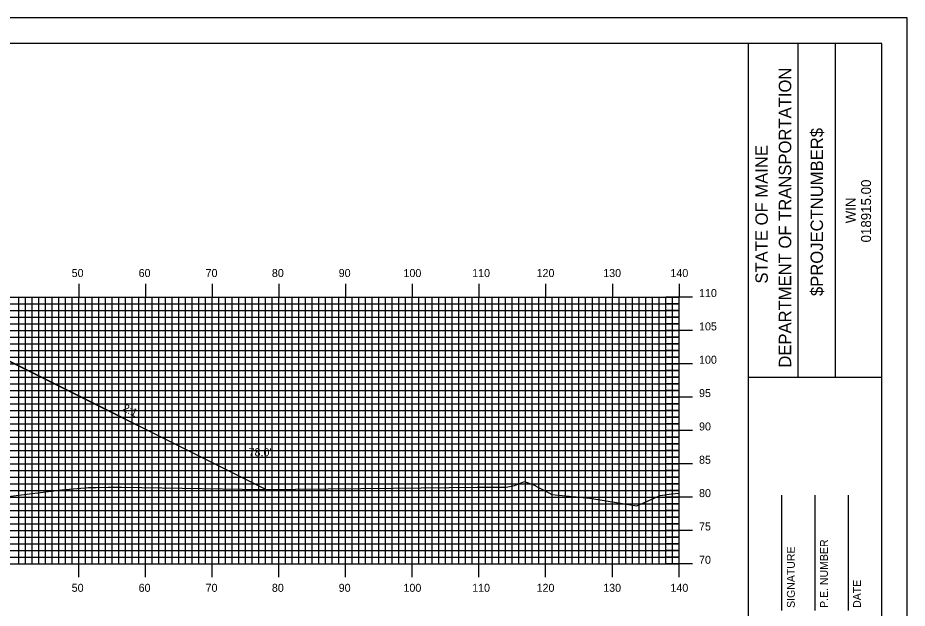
# Model space of a CAD drawing. Extents: x 1759036 to 1759380, y 442591 to 442811.
# Drawn here: x 1759243 to 1759376.4, y 442722 to 442810.5 of the extents above; entities that cross this region are included whole.
import ezdxf

# ---------------------------------------------------------------- set-up
doc = ezdxf.new("R2010")
doc.units = 0
for name, color, linetype in [('ANNOTATION', 7, 'Continuous'), ('BORDER', 7, 'Continuous'), ('D_Roadway_Centerline', 7, 'Continuous'), ('D_Roadway_SlopeLines', 7, 'Continuous'), ('D_Text_Standard', 7, 'Continuous'), ('H_V ANNOTATION', 7, 'Continuous'), ('MAJOR', 7, 'Continuous'), ('MINOR', 7, 'Continuous'), ('PLOT BOUNDARY', 7, 'Continuous'), ('S_Roadway_Centerline', 7, 'Continuous')]:
    doc.layers.add(name, color=color, linetype=linetype)

msp = doc.modelspace()

# ---------------------------------------------------------------- linework, layer by layer
at = {"layer": 'BORDER'}
for p, q in [((1759352.56, 442596.67), (1759352.56, 442806.67)), ((1759360.02, 442756.66), (1759360.02, 442806.66)), ((1759365.61, 442756.66), (1759365.61, 442806.66)), ((1759352.56, 442756.65), (1759372.56, 442756.65)), ((1759357.56, 442721.67), (1759357.56, 442738.97)), ((1759362.56, 442721.67), (1759362.56, 442738.97)), ((1759367.56, 442721.67), (1759367.56, 442738.97))]:
    msp.add_line(p, q, dxfattribs=at)
msp.add_lwpolyline([(1759052.56, 442596.67), (1759372.56, 442596.67), (1759372.56, 442806.67), (1759052.56, 442806.67)], close=True, dxfattribs=at)
at = {"layer": 'D_Roadway_Centerline'}
msp.add_lwpolyline([(1759138.03, 442739.48), (1759173.87, 442757.4), (1759179.16, 442760.04), (1759182.16, 442760.16), (1759190.16, 442760.48), (1759202.16, 442760.91), (1759214.16, 442761.35), (1759226.16, 442761.78), (1759234.16, 442761.46), (1759237.16, 442761.34), (1759241.91, 442758.96), (1759280.16, 442739.84)], dxfattribs=at)
at = {"layer": 'D_Roadway_SlopeLines'}
msp.add_lwpolyline([(1759237.16, 442761.34), (1759280.16, 442739.84)], dxfattribs=at)
at = {"layer": 'MAJOR'}
for p, q in [((1759252.16, 442770.67), (1759252.16, 442768.67)), ((1759262.16, 442770.67), (1759262.16, 442768.67)), ((1759272.16, 442770.67), (1759272.16, 442768.67)), ((1759282.16, 442770.67), (1759282.16, 442768.67)), ((1759292.16, 442770.67), (1759292.16, 442768.67)), ((1759302.16, 442770.67), (1759302.16, 442768.67)), ((1759312.16, 442770.67), (1759312.16, 442768.67)), ((1759322.16, 442770.67), (1759322.16, 442768.67)), ((1759332.16, 442770.67), (1759332.16, 442768.67)), ((1759342.16, 442770.67), (1759342.16, 442768.67)), ((1759062.16, 442768.67), (1759342.16, 442768.67)), ((1759062.16, 442768.67), (1759342.16, 442768.67)), ((1759252.16, 442728.67), (1759252.16, 442768.67)), ((1759262.16, 442728.67), (1759262.16, 442768.67)), ((1759272.16, 442728.67), (1759272.16, 442768.67)), ((1759282.16, 442728.67), (1759282.16, 442768.67)), ((1759292.16, 442728.67), (1759292.16, 442768.67)), ((1759302.16, 442728.67), (1759302.16, 442768.67)), ((1759312.16, 442728.67), (1759312.16, 442768.67)), ((1759322.16, 442728.67), (1759322.16, 442768.67)), ((1759332.16, 442728.67), (1759332.16, 442768.67)), ((1759344.17, 442768.67), (1759340.16, 442768.67)), ((1759342.16, 442728.67), (1759342.16, 442768.67)), ((1759342.16, 442728.67), (1759342.16, 442768.67)), ((1759062.16, 442763.67), (1759342.16, 442763.67)), ((1759344.17, 442763.67), (1759340.16, 442763.67)), ((1759062.16, 442758.67), (1759342.16, 442758.67)), ((1759344.17, 442758.67), (1759340.16, 442758.67)), ((1759062.16, 442753.67), (1759342.16, 442753.67)), ((1759344.17, 442753.67), (1759340.16, 442753.67)), ((1759062.16, 442748.67), (1759342.16, 442748.67)), ((1759344.17, 442748.67), (1759340.16, 442748.67)), ((1759062.16, 442743.67), (1759342.16, 442743.67)), ((1759344.17, 442743.67), (1759340.16, 442743.67)), ((1759062.16, 442738.67), (1759342.16, 442738.67)), ((1759344.17, 442738.67), (1759340.16, 442738.67)), ((1759062.16, 442733.67), (1759342.16, 442733.67)), ((1759344.17, 442733.67), (1759340.16, 442733.67)), ((1759062.16, 442728.67), (1759342.16, 442728.67)), ((1759062.16, 442728.67), (1759342.16, 442728.67)), ((1759252.16, 442726.66), (1759252.16, 442728.67)), ((1759262.16, 442726.66), (1759262.16, 442728.67)), ((1759272.16, 442726.66), (1759272.16, 442728.67)), ((1759282.16, 442726.66), (1759282.16, 442728.67)), ((1759292.16, 442726.66), (1759292.16, 442728.67)), ((1759302.16, 442726.66), (1759302.16, 442728.67)), ((1759312.16, 442726.66), (1759312.16, 442728.67)), ((1759322.16, 442726.66), (1759322.16, 442728.67)), ((1759332.16, 442726.66), (1759332.16, 442728.67)), ((1759344.17, 442728.67), (1759340.16, 442728.67)), ((1759342.16, 442726.66), (1759342.16, 442728.67))]:
    msp.add_line(p, q, dxfattribs=at)
at = {"layer": 'MINOR'}
for p, q in [((1759243.16, 442728.67), (1759243.16, 442768.67)), ((1759244.16, 442728.67), (1759244.16, 442768.67)), ((1759245.16, 442728.67), (1759245.16, 442768.67)), ((1759246.16, 442728.67), (1759246.16, 442768.67)), ((1759247.16, 442728.67), (1759247.16, 442768.67)), ((1759248.16, 442728.67), (1759248.16, 442768.67)), ((1759249.16, 442728.67), (1759249.16, 442768.67)), ((1759250.16, 442728.67), (1759250.16, 442768.67)), ((1759251.16, 442728.67), (1759251.16, 442768.67)), ((1759253.16, 442728.67), (1759253.16, 442768.67)), ((1759254.16, 442728.67), (1759254.16, 442768.67)), ((1759255.16, 442728.67), (1759255.16, 442768.67)), ((1759256.16, 442728.67), (1759256.16, 442768.67)), ((1759257.16, 442728.67), (1759257.16, 442768.67)), ((1759258.16, 442728.67), (1759258.16, 442768.67)), ((1759259.16, 442728.67), (1759259.16, 442768.67)), ((1759260.16, 442728.67), (1759260.16, 442768.67)), ((1759261.16, 442728.67), (1759261.16, 442768.67)), ((1759263.16, 442728.67), (1759263.16, 442768.67)), ((1759264.16, 442728.67), (1759264.16, 442768.67)), ((1759265.16, 442728.67), (1759265.16, 442768.67)), ((1759266.16, 442728.67), (1759266.16, 442768.67)), ((1759267.16, 442728.67), (1759267.16, 442768.67)), ((1759268.16, 442728.67), (1759268.16, 442768.67)), ((1759269.16, 442728.67), (1759269.16, 442768.67)), ((1759270.16, 442728.67), (1759270.16, 442768.67)), ((1759271.16, 442728.67), (1759271.16, 442768.67)), ((1759273.16, 442728.67), (1759273.16, 442768.67)), ((1759274.16, 442728.67), (1759274.16, 442768.67)), ((1759275.16, 442728.67), (1759275.16, 442768.67)), ((1759276.16, 442728.67), (1759276.16, 442768.67)), ((1759277.16, 442728.67), (1759277.16, 442768.67)), ((1759278.16, 442728.67), (1759278.16, 442768.67)), ((1759279.16, 442728.67), (1759279.16, 442768.67)), ((1759280.16, 442728.67), (1759280.16, 442768.67)), ((1759281.16, 442728.67), (1759281.16, 442768.67)), ((1759283.16, 442728.67), (1759283.16, 442768.67)), ((1759284.16, 442728.67), (1759284.16, 442768.67)), ((1759285.16, 442728.67), (1759285.16, 442768.67)), ((1759286.16, 442728.67), (1759286.16, 442768.67)), ((1759287.16, 442728.67), (1759287.16, 442768.67)), ((1759288.16, 442728.67), (1759288.16, 442768.67)), ((1759289.16, 442728.67), (1759289.16, 442768.67)), ((1759290.16, 442728.67), (1759290.16, 442768.67)), ((1759291.16, 442728.67), (1759291.16, 442768.67)), ((1759293.16, 442728.67), (1759293.16, 442768.67)), ((1759294.16, 442728.67), (1759294.16, 442768.67)), ((1759295.16, 442728.67), (1759295.16, 442768.67)), ((1759296.16, 442728.67), (1759296.16, 442768.67)), ((1759297.16, 442728.67), (1759297.16, 442768.67)), ((1759298.16, 442728.67), (1759298.16, 442768.67)), ((1759299.16, 442728.67), (1759299.16, 442768.67)), ((1759300.16, 442728.67), (1759300.16, 442768.67)), ((1759301.16, 442728.67), (1759301.16, 442768.67)), ((1759303.16, 442728.67), (1759303.16, 442768.67)), ((1759304.16, 442728.67), (1759304.16, 442768.67)), ((1759305.16, 442728.67), (1759305.16, 442768.67)), ((1759306.16, 442728.67), (1759306.16, 442768.67)), ((1759307.16, 442728.67), (1759307.16, 442768.67)), ((1759308.16, 442728.67), (1759308.16, 442768.67)), ((1759309.16, 442728.67), (1759309.16, 442768.67)), ((1759310.16, 442728.67), (1759310.16, 442768.67)), ((1759311.16, 442728.67), (1759311.16, 442768.67)), ((1759313.16, 442728.67), (1759313.16, 442768.67)), ((1759314.16, 442728.67), (1759314.16, 442768.67)), ((1759315.16, 442728.67), (1759315.16, 442768.67)), ((1759316.16, 442728.67), (1759316.16, 442768.67)), ((1759317.16, 442728.67), (1759317.16, 442768.67)), ((1759318.16, 442728.67), (1759318.16, 442768.67)), ((1759319.16, 442728.67), (1759319.16, 442768.67)), ((1759320.16, 442728.67), (1759320.16, 442768.67)), ((1759321.16, 442728.67), (1759321.16, 442768.67)), ((1759323.16, 442728.67), (1759323.16, 442768.67)), ((1759324.16, 442728.67), (1759324.16, 442768.67)), ((1759325.16, 442728.67), (1759325.16, 442768.67)), ((1759326.16, 442728.67), (1759326.16, 442768.67)), ((1759327.16, 442728.67), (1759327.16, 442768.67)), ((1759328.16, 442728.67), (1759328.16, 442768.67)), ((1759329.16, 442728.67), (1759329.16, 442768.67)), ((1759330.16, 442728.67), (1759330.16, 442768.67)), ((1759331.16, 442728.67), (1759331.16, 442768.67)), ((1759333.16, 442728.67), (1759333.16, 442768.67)), ((1759334.16, 442728.67), (1759334.16, 442768.67)), ((1759335.16, 442728.67), (1759335.16, 442768.67)), ((1759336.16, 442728.67), (1759336.16, 442768.67)), ((1759337.16, 442728.67), (1759337.16, 442768.67)), ((1759338.16, 442728.67), (1759338.16, 442768.67)), ((1759339.16, 442728.67), (1759339.16, 442768.67)), ((1759340.16, 442728.67), (1759340.16, 442768.67)), ((1759341.16, 442728.67), (1759341.16, 442768.67)), ((1759062.16, 442767.67), (1759342.16, 442767.67)), ((1759342.16, 442767.67), (1759340.16, 442767.67)), ((1759062.16, 442766.67), (1759342.16, 442766.67)), ((1759342.16, 442766.67), (1759340.16, 442766.67)), ((1759062.16, 442765.67), (1759342.16, 442765.67)), ((1759062.16, 442764.67), (1759342.16, 442764.67)), ((1759342.16, 442765.67), (1759340.16, 442765.67)), ((1759342.16, 442764.67), (1759340.16, 442764.67)), ((1759062.16, 442762.67), (1759342.16, 442762.67)), ((1759342.16, 442762.67), (1759340.16, 442762.67)), ((1759062.16, 442761.67), (1759342.16, 442761.67)), ((1759062.16, 442760.67), (1759342.16, 442760.67)), ((1759342.16, 442761.67), (1759340.16, 442761.67)), ((1759342.16, 442760.67), (1759340.16, 442760.67)), ((1759062.16, 442759.67), (1759342.16, 442759.67)), ((1759342.16, 442759.67), (1759340.16, 442759.67)), ((1759062.16, 442757.67), (1759342.16, 442757.67)), ((1759062.16, 442756.67), (1759342.16, 442756.67)), ((1759342.16, 442757.67), (1759340.16, 442757.67)), ((1759342.16, 442756.67), (1759340.16, 442756.67)), ((1759062.16, 442755.67), (1759342.16, 442755.67)), ((1759342.16, 442755.67), (1759340.16, 442755.67)), ((1759062.16, 442754.67), (1759342.16, 442754.67)), ((1759342.16, 442754.67), (1759340.16, 442754.67)), ((1759062.16, 442752.67), (1759342.16, 442752.67)), ((1759342.16, 442752.67), (1759340.16, 442752.67)), ((1759062.16, 442751.67), (1759342.16, 442751.67)), ((1759342.16, 442751.67), (1759340.16, 442751.67)), ((1759062.16, 442750.67), (1759342.16, 442750.67)), ((1759342.16, 442750.67), (1759340.16, 442750.67)), ((1759062.16, 442749.67), (1759342.16, 442749.67)), ((1759342.16, 442749.67), (1759340.16, 442749.67)), ((1759062.16, 442747.67), (1759342.16, 442747.67)), ((1759342.16, 442747.67), (1759340.16, 442747.67)), ((1759062.16, 442746.67), (1759342.16, 442746.67)), ((1759342.16, 442746.67), (1759340.16, 442746.67)), ((1759062.16, 442745.67), (1759342.16, 442745.67)), ((1759062.16, 442744.67), (1759342.16, 442744.67)), ((1759342.16, 442745.67), (1759340.16, 442745.67)), ((1759342.16, 442744.67), (1759340.16, 442744.67)), ((1759062.16, 442742.67), (1759342.16, 442742.67)), ((1759342.16, 442742.67), (1759340.16, 442742.67)), ((1759062.16, 442741.67), (1759342.16, 442741.67)), ((1759062.16, 442740.67), (1759342.16, 442740.67)), ((1759342.16, 442741.67), (1759340.16, 442741.67)), ((1759342.16, 442740.67), (1759340.16, 442740.67)), ((1759062.16, 442739.67), (1759342.16, 442739.67)), ((1759342.16, 442739.67), (1759340.16, 442739.67)), ((1759062.16, 442737.67), (1759342.16, 442737.67)), ((1759062.16, 442736.67), (1759342.16, 442736.67)), ((1759342.16, 442737.67), (1759340.16, 442737.67)), ((1759342.16, 442736.67), (1759340.16, 442736.67)), ((1759062.16, 442735.67), (1759342.16, 442735.67)), ((1759342.16, 442735.67), (1759340.16, 442735.67)), ((1759062.16, 442734.67), (1759342.16, 442734.67)), ((1759342.16, 442734.67), (1759340.16, 442734.67)), ((1759062.16, 442732.67), (1759342.16, 442732.67)), ((1759342.16, 442732.67), (1759340.16, 442732.67)), ((1759062.16, 442731.67), (1759342.16, 442731.67)), ((1759342.16, 442731.67), (1759340.16, 442731.67)), ((1759062.16, 442730.67), (1759342.16, 442730.67)), ((1759342.16, 442730.67), (1759340.16, 442730.67)), ((1759062.16, 442729.67), (1759342.16, 442729.67)), ((1759342.16, 442729.67), (1759340.16, 442729.67))]:
    msp.add_line(p, q, dxfattribs=at)
at = {"layer": 'PLOT BOUNDARY'}
msp.add_lwpolyline([(1759036.37, 442590.55), (1759376.37, 442590.55), (1759376.37, 442810.55), (1759036.37, 442810.55)], close=True, dxfattribs=at)
at = {"layer": 'S_Roadway_Centerline'}
msp.add_lwpolyline([(1759241.56, 442738.74), (1759249.63, 442739.75), (1759253.6, 442740.09), (1759254.77, 442740.13), (1759256.63, 442740.14), (1759258.56, 442740.15), (1759279.76, 442739.83), (1759294.46, 442739.98), (1759299.3, 442740.03), (1759311.9, 442740.17), (1759316.25, 442740.15), (1759317.47, 442740.39), (1759318.97, 442741.03), (1759320.49, 442740.46), (1759320.62, 442740.4), (1759320.7, 442740.31), (1759322.08, 442739.62), (1759323.11, 442739.07), (1759328.76, 442738.53), (1759335.84, 442737.37), (1759339.34, 442738.9), (1759341.03, 442739.15), (1759342.16, 442739.26)], dxfattribs=at)

# ---------------------------------------------------------------- texts
at = {"layer": 'ANNOTATION'}
msp.add_text('2:1', height=1.2, rotation=333.4349, dxfattribs=at).set_placement((1759258.6, 442751.66))
at = {"layer": 'BORDER'}
for s, height, p in [('DEPARTMENT OF TRANSPORTATION', 1.8635, (1759358.98, 442758.08)), ('$PROJECTNUMBER$', 1.8635, (1759363.75, 442768.82)), ('STATE OF MAINE', 1.8635, (1759355.47, 442770.69)), ('018915.00', 1.491, (1759370.95, 442776.86)), ('WIN', 1.491, (1759368.63, 442779.73)), ('P.E. NUMBER', 1.1811, (1759364.48, 442722.06)), ('SIGNATURE', 1.181, (1759359.52, 442722.06)), ('DATE', 1.181, (1759369.44, 442722.06))]:
    msp.add_text(s, height=height, rotation=90, dxfattribs=at).set_placement(p)
at = {"layer": 'D_Text_Standard'}
msp.add_text("78.0'", height=1.2, dxfattribs=at).set_placement((1759277.62, 442744.8))
at = {"layer": 'H_V ANNOTATION'}
for s, p in [('50', (1759251.09, 442771.67)), ('60', (1759261.13, 442771.67)), ('70', (1759271.17, 442771.67)), ('80', (1759281.11, 442771.67)), ('90', (1759291.13, 442771.67)), ('100', (1759300.84, 442771.67)), ('110', (1759311.14, 442771.67)), ('120', (1759320.8, 442771.67)), ('130', (1759330.79, 442771.67)), ('140', (1759340.87, 442771.67)), ('110', (1759345.16, 442768.67)), ('105', (1759345.16, 442763.67)), ('100', (1759345.16, 442758.67)), ('95', (1759345.16, 442753.67)), ('90', (1759345.16, 442748.67)), ('85', (1759345.16, 442743.67)), ('80', (1759345.16, 442738.67)), ('75', (1759345.16, 442733.67)), ('70', (1759345.16, 442728.67)), ('50', (1759251.09, 442724.47)), ('60', (1759261.13, 442724.47)), ('70', (1759271.17, 442724.47)), ('80', (1759281.11, 442724.47)), ('90', (1759291.13, 442724.47)), ('100', (1759300.84, 442724.47)), ('110', (1759311.14, 442724.47)), ('120', (1759320.8, 442724.47)), ('130', (1759330.79, 442724.47)), ('140', (1759340.87, 442724.47))]:
    msp.add_text(s, height=1.2, dxfattribs=at).set_placement(p)

doc.saveas('drawing.dxf')
